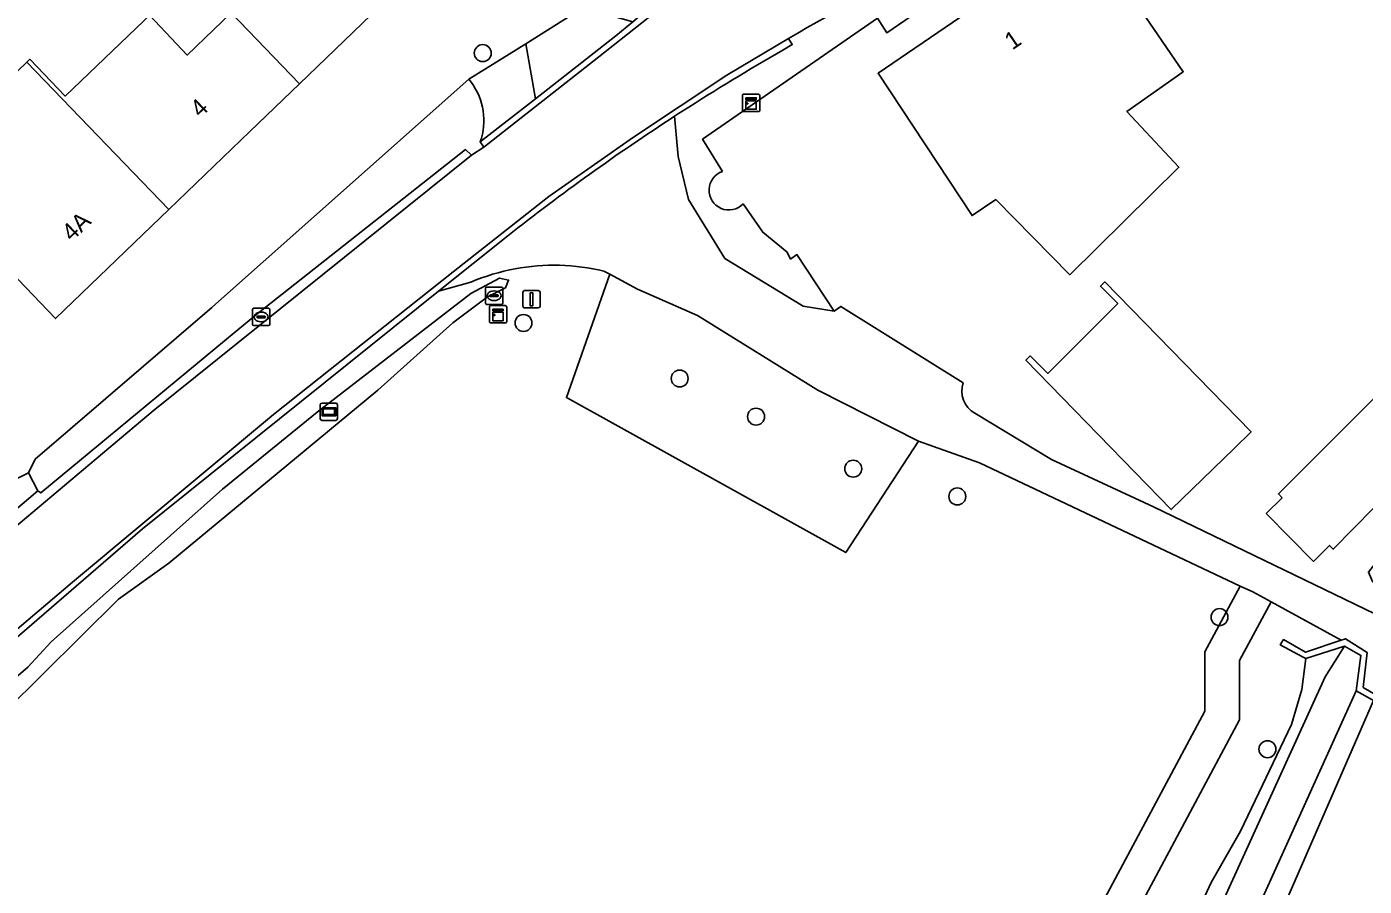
# Model space of a CAD drawing. Extents: x 164494 to 166241, y 382475 to 384495.
# Drawn here: x 165354.5 to 165431.6, y 384025.1 to 384074.7 of the extents above; entities that cross this region are included whole.
import ezdxf

# ---------------------------------------------------------------- set-up
doc = ezdxf.new("R2010")
doc.units = 0
for name, color, linetype in [('IMGEO_Berm_halfverhard', 7, 'Continuous'), ('IMGEO_Berm_open', 7, 'Continuous'), ('IMGEO_Boom', 7, 'Continuous'), ('IMGEO_Erf', 7, 'Continuous'), ('IMGEO_Grasland_agrarisch', 7, 'Continuous'), ('IMGEO_Grasland_overig', 7, 'Continuous'), ('IMGEO_Groenvoorziening', 7, 'Continuous'), ('IMGEO_Kast', 7, 'Continuous'), ('IMGEO_Kolk', 7, 'Continuous'), ('IMGEO_Muur', 7, 'Continuous'), ('IMGEO_Oever', 7, 'Continuous'), ('IMGEO_Pand', 7, 'Continuous'), ('IMGEO_Pand_nummerreeks', 7, 'Continuous'), ('IMGEO_Rijbaan_lokaal_gesloten', 7, 'Continuous'), ('IMGEO_Rioolput', 7, 'Continuous'), ('IMGEO_Verkeersbordpaal', 7, 'Continuous'), ('IMGEO_Voetpad_halfverhard', 7, 'Continuous'), ('IMGEO_Voetpad_open', 7, 'Continuous'), ('IMGEO_Waterloop', 7, 'Continuous'), ('IMGEO_Wegwijzer', 7, 'Continuous')]:
    doc.layers.add(name, color=color, linetype=linetype)

msp = doc.modelspace()

# ---------------------------------------------------------------- linework, layer by layer
at = {"layer": 'IMGEO_Berm_halfverhard'}
for points in [[(165394.648, 384079.364), (165394.369, 384079.637), (165392.734, 384077.813), (165390.73, 384076.059), (165389.436, 384074.97), (165388.458, 384074.147), (165383.832, 384070.529), (165380.649, 384068.04), (165380.854, 384067.745), (165387.482, 384072.953), (165391.605, 384076.232)], [(165398.089, 384073.33), (165398.624, 384073.651), (165398.403, 384074.002), (165394.851, 384071.884), (165389.473, 384068.311), (165384.606, 384064.9), (165379.087, 384060.555), (165368.742, 384052.317), (165357.153, 384042.664), (165349.337, 384036.022), (165342.774, 384030.162), (165342.196, 384029.629), (165342.457, 384029.327), (165343.149, 384029.924), (165343.032, 384030.052), (165361.191, 384045.73)], [(165391.847, 384069.519), (165392.081, 384069.671), (165392.316, 384069.823)], [(165361.191, 384045.73), (165378.251, 384059.429), (165382.228, 384062.623)]]:
    msp.add_lwpolyline(points, dxfattribs=at)
for centre, radius, start, end in [((165462.902, 383960.133), 130.439, 119.79428, 122.76167), ((165462.493, 383960.82), 129.639, 123.02094, 128.25363)]:
    msp.add_arc(centre, radius, start, end, dxfattribs=at)
at = {"layer": 'IMGEO_Berm_open'}
msp.add_lwpolyline([(165380.141, 384067.277), (165379.794, 384067.601), (165367.867, 384058.185), (165366.467, 384057.026), (165355.319, 384047.804), (165355.158, 384047.926), (165353.349, 384046.386), (165353.618, 384046.006), (165353.778, 384045.772), (165361.803, 384052.529)], close=True, dxfattribs=at)
at = {"layer": 'IMGEO_Boom'}
for centre in [(165380.789, 384073.159), (165383.14, 384057.6), (165392.14, 384054.4), (165396.54, 384052.2), (165402.14, 384049.2), (165408.14, 384047.6), (165423.25, 384040.641), (165426.014, 384033.026)]:
    msp.add_circle(centre, 0.489, dxfattribs=at)
at = {"layer": 'IMGEO_Erf'}
for points in [[(165370.222, 384071.391), (165367.373, 384068.646), (165362.702, 384064.146), (165361.201, 384062.699), (165356.175, 384057.856), (165352.706, 384061.457), (165347.988, 384066.354), (165354.518, 384072.645), (165354.686, 384072.807), (165356.732, 384070.685), (165361.259, 384075.024), (165361.593, 384075.344), (165361.693, 384075.439), (165359.686, 384077.533), (165370.419, 384087.822), (165372.426, 384085.728), (165378.512, 384079.379)], [(165424.097, 384050.371), (165420.472, 384046.84), (165412.096, 384055.45), (165412.344, 384055.698), (165413.347, 384054.691), (165417.389, 384058.715), (165416.387, 384059.721), (165416.635, 384059.967), (165425.071, 384051.32)], [(165425.935, 384046.612), (165426.859, 384047.528), (165426.648, 384047.742), (165433.701, 384054.796), (165436.839, 384051.712), (165429.803, 384044.559), (165429.591, 384044.772), (165428.667, 384043.856)]]:
    msp.add_lwpolyline(points, close=True, dxfattribs=at)
for points in [[(165452.198, 384086.5), (165450.367, 384088.075), (165420.581, 384081.409), (165419.584, 384082.942), (165415.596, 384080.216), (165421.157, 384072.086), (165417.913, 384069.799), (165420.915, 384066.582), (165414.624, 384060.384), (165410.357, 384064.715), (165408.991, 384063.791), (165403.577, 384071.996), (165413.421, 384078.728), (165412.998, 384079.325), (165412.511, 384080.132), (165404.074, 384074.333), (165403.548, 384075.178), (165393.462, 384068.193), (165394.614, 384066.341)], [(165379.994, 384071.652), (165383.268, 384073.701), (165386.651, 384075.818), (165386.877, 384076.031), (165390.423, 384079.385), (165392.167, 384081.577)], [(165353.783, 384048.557), (165354.194, 384048.759), (165354.605, 384048.96), (165354.993, 384049.748), (165365.174, 384058.493), (165365.22, 384058.534), (165379.994, 384071.652)], [(165395.797, 384064.474), (165396.928, 384062.833), (165398.326, 384061.675), (165398.534, 384061.287), (165398.894, 384061.546), (165401.043, 384058.287), (165401.42, 384058.556), (165408.472, 384054.156)], [(165409.157, 384052.399), (165413.571, 384049.73), (165419.448, 384047.004), (165432.21, 384040.827), (165432.889, 384042.04), (165432.059, 384042.703), (165431.835, 384043.241), (165432.508, 384044.106), (165433.832, 384046.315), (165434.934, 384048.823), (165437.077, 384050.998), (165439.037, 384053.712), (165441.349, 384057.507)]]:
    msp.add_lwpolyline(points, dxfattribs=at)
for centre, radius, start, end in [((165394.97, 384065.258), 1.14, 108.1874, 316.5323), ((165409.863, 384053.686), 1.468, 161.33029, 241.26826)]:
    msp.add_arc(centre, radius, start, end, dxfattribs=at)
at = {"layer": 'IMGEO_Grasland_agrarisch'}
msp.add_lwpolyline([(165465.876, 383995.163), (165467.034, 384000), (165468.503, 384005.261), (165471.517, 384012.308), (165471.562, 384012.413), (165472.114, 384013.698), (165433.758, 384035.364), (165432.127, 384035.844), (165425.699, 384021.103), (165420.906, 384009.219), (165420.603, 384008.641), (165397.653, 383961.837), (165387.56, 383941.909), (165384.176, 383935.455), (165366.719, 383898.707), (165373.354, 383895.442), (165395.688, 383886.318), (165424.197, 383875.062), (165430.956, 383872.05), (165432.029, 383878.537), (165432.519, 383879.96)], close=True, dxfattribs=at)
at = {"layer": 'IMGEO_Grasland_overig'}
msp.add_lwpolyline([(165406.11, 384000.476), (165424.408, 384034.719), (165424.408, 384038.135), (165426.221, 384041.519), (165425.166, 384042.094), (165424.443, 384042.436), (165422.408, 384038.636), (165422.408, 384035.22), (165404.241, 384001.221)], close=True, dxfattribs=at)
at = {"layer": 'IMGEO_Groenvoorziening'}
for points in [[(165394.614, 384066.341), (165393.462, 384068.193), (165403.548, 384075.178), (165404.074, 384074.333), (165412.511, 384080.132), (165412.998, 384079.325), (165413.421, 384078.728), (165415.596, 384080.216), (165419.584, 384082.942), (165420.581, 384081.409), (165450.367, 384088.075), (165452.198, 384086.5)], [(165383.268, 384073.701), (165379.994, 384071.652)], [(165380.718, 384068.254), (165380.649, 384068.04), (165383.832, 384070.529), (165383.268, 384073.701)], [(165398.403, 384074.002), (165398.624, 384073.651), (165398.089, 384073.33)], [(165392.316, 384069.823), (165392.081, 384069.671), (165391.847, 384069.519), (165392.047, 384067.198), (165392.645, 384064.723), (165394.748, 384061.318), (165399.265, 384058.57), (165401.043, 384058.287), (165398.894, 384061.546), (165398.534, 384061.287), (165398.326, 384061.675), (165396.928, 384062.833), (165395.797, 384064.474)], [(165404.241, 384001.221), (165422.408, 384035.22), (165422.408, 384038.636), (165424.443, 384042.436), (165409.423, 384049.542), (165405.906, 384050.785), (165401.71, 384044.364), (165385.614, 384053.302), (165388.113, 384060.405), (165387.776, 384060.588)], [(165380.105, 384059.954), (165378.251, 384059.429), (165361.191, 384045.73), (165343.032, 384030.052), (165343.149, 384029.924), (165342.457, 384029.327), (165328.664, 384017.425), (165327.921, 384016.784), (165327.858, 384016.829), (165300.992, 383993.615)], [(165333.093, 384019.286), (165354.573, 384037.755), (165355.922, 384039.225), (165365.795, 384048.014), (165371.241, 384052.452), (165380.109, 384059.294), (165381.762, 384060.186), (165382.283, 384060.069), (165382.106, 384059.628), (165381.07, 384059.101), (165379.062, 384057.607), (165374.751, 384053.736), (165362.707, 384043.753), (165359.803, 384041.672), (165346.76, 384028.762), (165343.024, 384025.615), (165348.876, 384023.417)], [(165325.135, 384021.562), (165338.914, 384033.424), (165339.626, 384034.037), (165339.695, 384033.942), (165353.618, 384046.006), (165353.349, 384046.386), (165355.158, 384047.926), (165354.605, 384048.96), (165354.194, 384048.759), (165353.783, 384048.557), (165342.506, 384038.557), (165341.59, 384039.543), (165339.009, 384037.144), (165338.707, 384036.864), (165339.33, 384036.181), (165338.418, 384035.282), (165337.958, 384035.319), (165337.536, 384035.616), (165337.481, 384035.681), (165335.45, 384033.721), (165335.536, 384032.942), (165328.461, 384026.792), (165318.663, 384018.644)]]:
    msp.add_lwpolyline(points, dxfattribs=at)
for points in [[(165388.113, 384060.405), (165385.614, 384053.302), (165401.71, 384044.364), (165405.906, 384050.785), (165400.098, 384053.736), (165393.172, 384058.027), (165389.703, 384059.542)], [(165422.766, 384025.338), (165424.464, 384028.31), (165427.399, 384034.45), (165427.985, 384036.474), (165428.232, 384038.256), (165428.079, 384038.337), (165426.748, 384039.045), (165426.938, 384039.344), (165428.209, 384038.616), (165430.27, 384039.313), (165426.221, 384041.519), (165424.408, 384038.135), (165424.408, 384034.719), (165406.11, 384000.476), (165407.304, 384000), (165408.115, 383999.677), (165409.877, 383999.369), (165410.163, 384000), (165411.412, 384002.76), (165415.793, 384011.089), (165416.075, 384011.624), (165418.888, 384016.972)]]:
    msp.add_lwpolyline(points, close=True, dxfattribs=at)
for centre, radius, start, end in [((165456.825, 383973.925), 115.881, 110.3071, 120.27508), ((165462.902, 383960.133), 130.439, 119.79428, 122.76167), ((165377.139, 384069.268), 3.72, 344.18976, 39.86614), ((165394.97, 384065.258), 1.14, 108.1874, 316.5323), ((165384.913, 384048.624), 12.308, 100.59261, 112.99168), ((165384.899, 384048.625), 12.304, 76.4753, 100.52981)]:
    msp.add_arc(centre, radius, start, end, dxfattribs=at)
at = {"layer": 'IMGEO_Kast'}
for p, q in [((165395.756, 384069.867), (165395.756, 384070.708)), ((165395.756, 384070.708), (165395.756, 384069.867)), ((165395.831, 384070.792), (165396.672, 384070.792)), ((165396.672, 384070.792), (165395.831, 384070.792)), ((165396.756, 384070.717), (165396.756, 384069.876)), ((165396.756, 384069.876), (165396.756, 384070.717)), ((165396.681, 384069.792), (165395.84, 384069.792)), ((165395.84, 384069.792), (165396.681, 384069.792)), ((165381.173, 384057.676), (165381.173, 384058.517)), ((165381.173, 384058.517), (165381.173, 384057.676)), ((165381.248, 384058.601), (165382.089, 384058.601)), ((165382.089, 384058.601), (165381.248, 384058.601)), ((165382.173, 384058.526), (165382.173, 384057.685)), ((165382.173, 384057.685), (165382.173, 384058.526)), ((165382.098, 384057.601), (165381.257, 384057.601)), ((165381.257, 384057.601), (165382.098, 384057.601))]:
    msp.add_line(p, q, dxfattribs=at)
for points in [[(165395.951, 384070.582), (165396.551, 384070.582), (165396.551, 384070.497), (165395.951, 384070.497), (165395.951, 384070.582)], [(165395.951, 384070.407), (165396.551, 384070.407), (165396.551, 384069.918), (165395.951, 384069.918), (165395.951, 384070.407)], [(165381.368, 384058.391), (165381.968, 384058.391), (165381.968, 384058.306), (165381.368, 384058.306), (165381.368, 384058.391)], [(165381.368, 384058.216), (165381.968, 384058.216), (165381.968, 384057.727), (165381.368, 384057.727), (165381.368, 384058.216)]]:
    msp.add_lwpolyline(points, dxfattribs=at)
for centre in [(165396.035, 384070.256), (165381.452, 384058.065)]:
    msp.add_circle(centre, 0.0377, dxfattribs=at)
for centre, start, end in [((165395.834, 384070.714), 92.4484, 184.28452), ((165395.834, 384070.714), 92.4484, 184.28452), ((165396.678, 384070.714), 2.4484, 94.28452), ((165396.678, 384070.714), 2.4484, 94.28452), ((165395.834, 384069.87), 182.4484, 274.28452), ((165395.834, 384069.87), 182.4484, 274.28452), ((165396.678, 384069.87), 272.4484, 4.28452), ((165396.678, 384069.87), 272.4484, 4.28452), ((165381.251, 384058.523), 92.4484, 184.28452), ((165381.251, 384058.523), 92.4484, 184.28452), ((165382.095, 384058.523), 2.4484, 94.28452), ((165382.095, 384058.523), 2.4484, 94.28452), ((165381.251, 384057.679), 182.4484, 274.28452), ((165381.251, 384057.679), 182.4484, 274.28452), ((165382.095, 384057.679), 272.4484, 4.28452), ((165382.095, 384057.679), 272.4484, 4.28452)]:
    msp.add_arc(centre, 0.0779, start, end, dxfattribs=at)
at = {"layer": 'IMGEO_Kolk'}
for p, q in [((165367.52, 384057.521), (165367.52, 384058.373)), ((165367.595, 384058.447), (165368.447, 384058.447)), ((165368.008, 384058.227), (165368.033, 384058.227)), ((165368.521, 384058.373), (165368.521, 384057.521)), ((165368.447, 384057.447), (165367.595, 384057.447)), ((165367.779, 384057.941), (165367.779, 384057.953)), ((165368.217, 384057.904), (165367.819, 384057.904)), ((165367.822, 384057.99), (165368.22, 384057.99)), ((165368.031, 384057.667), (165368.006, 384057.667)), ((165368.263, 384057.953), (165368.263, 384057.941))]:
    msp.add_line(p, q, dxfattribs=at)
for points in [[(165367.52, 384057.521), (165367.52, 384058.373)], [(165367.595, 384058.447), (165368.447, 384058.447)], [(165368.521, 384058.373), (165368.521, 384057.521)], [(165368.447, 384057.447), (165367.595, 384057.447)]]:
    msp.add_lwpolyline(points, dxfattribs=at)
for centre, radius, start, end in [((165367.597, 384058.371), 0.0765, 91.55205, 178.44795), ((165367.597, 384058.371), 0.0765, 91.55205, 178.44795), ((165368.445, 384058.371), 0.0765, 1.55205, 88.44795), ((165368.445, 384058.371), 0.0765, 1.55205, 88.44795), ((165367.597, 384057.523), 0.0765, 181.55205, 268.44795), ((165367.597, 384057.523), 0.0765, 181.55205, 268.44795), ((165367.819, 384057.95), 0.0403, 85.87752, 175.75265), ((165367.816, 384057.94), 0.0366, 178.93798, 274.71019), ((165368.22, 384057.947), 0.043, 264.86636, 352.45326), ((165368.224, 384057.952), 0.0386, 1.73085, 96.63898), ((165368.445, 384057.523), 0.0765, 271.55205, 358.44795), ((165368.445, 384057.523), 0.0765, 271.55205, 358.44795)]:
    msp.add_arc(centre, radius, start, end, dxfattribs=at)
for centre, major_axis, ratio, start_param, end_param in [((165368.007, 384057.947), (-0.387, 0.002), 0.722429, 4.712389, 7.853982), ((165368.032, 384057.947), (-0.39, 0.002), 0.717154, 1.570796, 4.712389)]:
    msp.add_ellipse(centre, major_axis=major_axis, ratio=ratio, start_param=start_param, end_param=end_param, dxfattribs=at)
at = {"layer": 'IMGEO_Muur'}
msp.add_lwpolyline([(165428.079, 384038.337), (165428.232, 384038.256), (165430.446, 384038.958), (165431.397, 384038.432), (165431.116, 384036.401), (165432.127, 384035.844), (165432.264, 384036.165), (165431.524, 384036.587), (165431.768, 384038.601), (165430.503, 384039.392), (165430.27, 384039.313), (165428.209, 384038.616), (165426.938, 384039.344), (165426.748, 384039.045)], close=True, dxfattribs=at)
at = {"layer": 'IMGEO_Oever'}
for points in [[(165430.446, 384038.958), (165428.232, 384038.256), (165427.985, 384036.474), (165427.399, 384034.45), (165424.464, 384028.31), (165422.766, 384025.338), (165418.888, 384016.972), (165416.075, 384011.624), (165415.793, 384011.089), (165417.142, 384010.409), (165429.344, 384037.193)], [(165425.699, 384021.103), (165432.127, 384035.844), (165431.116, 384036.401), (165419.214, 384010.042), (165418.943, 384009.502), (165420.603, 384008.641), (165420.906, 384009.219)]]:
    msp.add_lwpolyline(points, close=True, dxfattribs=at)
at = {"layer": 'IMGEO_Pand'}
for points in [[(165378.512, 384079.379), (165372.426, 384085.728), (165370.419, 384087.822), (165359.686, 384077.533), (165361.693, 384075.439), (165361.593, 384075.344), (165363.752, 384073.045), (165366.29, 384075.484), (165370.222, 384071.391)], [(165413.421, 384078.728), (165403.577, 384071.996), (165408.991, 384063.791), (165410.357, 384064.715), (165414.624, 384060.384), (165420.915, 384066.582), (165417.913, 384069.799), (165421.157, 384072.086), (165415.596, 384080.216)], [(165362.702, 384064.146), (165367.373, 384068.646), (165370.222, 384071.391), (165366.29, 384075.484), (165363.752, 384073.045), (165361.593, 384075.344), (165361.259, 384075.024), (165356.732, 384070.685), (165354.686, 384072.807), (165354.518, 384072.645)], [(165362.702, 384064.146), (165354.518, 384072.645), (165347.988, 384066.354), (165352.706, 384061.457), (165356.175, 384057.856), (165361.201, 384062.699)], [(165424.097, 384050.371), (165425.071, 384051.32), (165416.635, 384059.967), (165416.387, 384059.721), (165417.389, 384058.715), (165413.347, 384054.691), (165412.344, 384055.698), (165412.096, 384055.45), (165420.472, 384046.84)], [(165425.935, 384046.612), (165428.667, 384043.856), (165429.591, 384044.772), (165429.803, 384044.559), (165436.839, 384051.712), (165433.701, 384054.796), (165426.648, 384047.742), (165426.859, 384047.528)]]:
    msp.add_lwpolyline(points, close=True, dxfattribs=at)
at = {"layer": 'IMGEO_Rijbaan_lokaal_gesloten'}
msp.add_lwpolyline([(165391.605, 384076.232), (165387.482, 384072.953), (165380.854, 384067.745), (165380.141, 384067.277), (165361.803, 384052.529), (165353.778, 384045.772), (165339.3, 384032.977), (165339.311, 384032.965), (165342.18, 384029.647), (165342.192, 384029.633), (165342.196, 384029.629), (165342.774, 384030.162), (165349.337, 384036.022), (165357.153, 384042.664), (165368.742, 384052.317), (165379.087, 384060.555), (165384.606, 384064.9), (165389.473, 384068.311), (165394.851, 384071.884), (165398.403, 384074.002)], dxfattribs=at)
msp.add_arc((165456.825, 383973.925), 115.881, 110.3071, 120.27508, dxfattribs=at)
at = {"layer": 'IMGEO_Rioolput'}
for p, q in [((165381.019, 384059.673), (165381.871, 384059.673)), ((165380.944, 384058.747), (165380.944, 384059.599)), ((165381.203, 384059.167), (165381.203, 384059.179)), ((165381.641, 384059.13), (165381.243, 384059.13)), ((165381.246, 384059.216), (165381.644, 384059.216)), ((165381.455, 384058.893), (165381.43, 384058.893)), ((165381.432, 384059.453), (165381.457, 384059.453)), ((165381.687, 384059.179), (165381.687, 384059.167)), ((165381.945, 384059.599), (165381.945, 384058.747)), ((165381.871, 384058.673), (165381.019, 384058.673))]:
    msp.add_line(p, q, dxfattribs=at)
for points in [[(165381.019, 384059.673), (165381.871, 384059.673)], [(165380.944, 384058.747), (165380.944, 384059.599)], [(165381.945, 384059.599), (165381.945, 384058.747)], [(165381.871, 384058.673), (165381.019, 384058.673)]]:
    msp.add_lwpolyline(points, dxfattribs=at)
for centre, radius, start, end in [((165381.021, 384059.597), 0.0765, 91.55205, 178.44795), ((165381.021, 384059.597), 0.0765, 91.55205, 178.44795), ((165381.869, 384059.597), 0.0765, 1.55205, 88.44795), ((165381.869, 384059.597), 0.0765, 1.55205, 88.44795), ((165381.243, 384059.176), 0.0403, 85.87752, 175.75265), ((165381.24, 384059.166), 0.0366, 178.93798, 274.71019), ((165381.644, 384059.173), 0.043, 264.86636, 352.45326), ((165381.648, 384059.178), 0.0386, 1.73085, 96.63898), ((165381.021, 384058.749), 0.0765, 181.55205, 268.44795), ((165381.021, 384058.749), 0.0765, 181.55205, 268.44795), ((165381.869, 384058.749), 0.0765, 271.55205, 358.44795), ((165381.869, 384058.749), 0.0765, 271.55205, 358.44795)]:
    msp.add_arc(centre, radius, start, end, dxfattribs=at)
for centre, major_axis, ratio, start_param, end_param in [((165381.431, 384059.173), (-0.387, 0.002), 0.722429, 4.712389, 7.853982), ((165381.456, 384059.173), (-0.39, 0.002), 0.717154, 1.570796, 4.712389)]:
    msp.add_ellipse(centre, major_axis=major_axis, ratio=ratio, start_param=start_param, end_param=end_param, dxfattribs=at)
at = {"layer": 'IMGEO_Verkeersbordpaal'}
for p, q in [((165383.103, 384058.572), (165383.103, 384059.372)), ((165383.103, 384059.372), (165383.103, 384058.572)), ((165383.203, 384059.472), (165383.993, 384059.472)), ((165383.993, 384059.472), (165383.203, 384059.472)), ((165384.093, 384059.372), (165384.093, 384058.572)), ((165384.093, 384058.572), (165384.093, 384059.372)), ((165383.993, 384058.472), (165383.203, 384058.472)), ((165383.203, 384058.472), (165383.993, 384058.472))]:
    msp.add_line(p, q, dxfattribs=at)
msp.add_lwpolyline([(165383.523, 384059.347), (165383.673, 384059.347), (165383.673, 384058.597), (165383.523, 384058.597), (165383.523, 384059.347)], dxfattribs=at)
for centre, start, end in [((165383.203, 384059.372), 90, 180), ((165383.203, 384059.372), 90, 180), ((165383.993, 384059.372), 0, 90), ((165383.993, 384059.372), 360, 90), ((165383.203, 384058.572), 180, 270), ((165383.203, 384058.572), 180, 270), ((165383.993, 384058.572), 270, 0), ((165383.993, 384058.572), 270, 0)]:
    msp.add_arc(centre, 0.1, start, end, dxfattribs=at)
at = {"layer": 'IMGEO_Voetpad_halfverhard'}
for points in [[(165408.472, 384054.156), (165401.42, 384058.556), (165401.043, 384058.287), (165399.265, 384058.57), (165394.748, 384061.318), (165392.645, 384064.723), (165392.047, 384067.198), (165391.847, 384069.519)], [(165382.228, 384062.623), (165378.251, 384059.429), (165380.105, 384059.954)], [(165387.776, 384060.588), (165388.113, 384060.405), (165389.703, 384059.542), (165393.172, 384058.027), (165400.098, 384053.736), (165405.906, 384050.785), (165409.423, 384049.542), (165424.443, 384042.436), (165425.166, 384042.094), (165426.221, 384041.519), (165430.27, 384039.313), (165430.503, 384039.392), (165431.768, 384038.601), (165431.524, 384036.587), (165432.264, 384036.165)], [(165419.448, 384047.004), (165413.571, 384049.73), (165409.157, 384052.399)], [(165432.21, 384040.827), (165419.448, 384047.004)]]:
    msp.add_lwpolyline(points, dxfattribs=at)
for centre, radius, start, end in [((165462.493, 383960.82), 129.639, 123.02094, 128.25363), ((165384.913, 384048.624), 12.308, 100.59261, 112.99168), ((165384.899, 384048.625), 12.304, 76.4753, 100.52981), ((165409.863, 384053.686), 1.468, 161.33029, 241.26826)]:
    msp.add_arc(centre, radius, start, end, dxfattribs=at)
at = {"layer": 'IMGEO_Voetpad_open'}
msp.add_lwpolyline([(165388.458, 384074.147), (165389.436, 384074.97), (165388.208, 384075.306), (165387.345, 384075.542), (165386.877, 384076.031), (165386.651, 384075.818), (165383.268, 384073.701), (165383.832, 384070.529)], close=True, dxfattribs=at)
for points in [[(165379.994, 384071.652), (165365.22, 384058.534), (165365.174, 384058.493), (165354.993, 384049.748), (165354.605, 384048.96), (165355.158, 384047.926), (165355.319, 384047.804), (165366.467, 384057.026), (165367.867, 384058.185)], [(165367.867, 384058.185), (165379.794, 384067.601), (165380.141, 384067.277), (165380.854, 384067.745), (165380.649, 384068.04), (165380.718, 384068.254)]]:
    msp.add_lwpolyline(points, dxfattribs=at)
msp.add_arc((165377.139, 384069.268), 3.72, 344.18976, 39.86614, dxfattribs=at)
at = {"layer": 'IMGEO_Waterloop'}
msp.add_lwpolyline([(165348.876, 384023.417), (165343.024, 384025.615), (165346.76, 384028.762), (165359.803, 384041.672), (165362.707, 384043.753), (165374.751, 384053.736), (165379.062, 384057.607), (165381.07, 384059.101), (165382.106, 384059.628), (165382.283, 384060.069), (165381.762, 384060.186), (165380.109, 384059.294), (165371.241, 384052.452), (165365.795, 384048.014), (165355.922, 384039.225), (165354.573, 384037.755), (165333.093, 384019.286)], dxfattribs=at)
msp.add_lwpolyline([(165431.116, 384036.401), (165431.397, 384038.432), (165430.446, 384038.958), (165429.344, 384037.193), (165417.142, 384010.409), (165418.943, 384009.502), (165419.214, 384010.042)], close=True, dxfattribs=at)
at = {"layer": 'IMGEO_Wegwijzer'}
for p, q in [((165371.428, 384052.083), (165371.428, 384052.883)), ((165371.428, 384052.883), (165371.428, 384052.083)), ((165371.528, 384052.983), (165372.318, 384052.983)), ((165372.318, 384052.983), (165371.528, 384052.983)), ((165372.418, 384052.883), (165372.418, 384052.083)), ((165372.418, 384052.083), (165372.418, 384052.883)), ((165372.318, 384051.983), (165371.528, 384051.983)), ((165371.528, 384051.983), (165372.318, 384051.983))]:
    msp.add_line(p, q, dxfattribs=at)
for points in [[(165371.529, 384052.715), (165372.317, 384052.715), (165372.317, 384052.251), (165371.529, 384052.251), (165371.529, 384052.715)], [(165371.594, 384052.65), (165371.594, 384052.316), (165372.252, 384052.316), (165372.252, 384052.65), (165371.594, 384052.65)]]:
    msp.add_lwpolyline(points, dxfattribs=at)
for centre, start, end in [((165371.528, 384052.883), 90, 180), ((165371.528, 384052.883), 90, 180), ((165372.318, 384052.883), 0, 90), ((165372.318, 384052.883), 360, 90), ((165371.528, 384052.083), 180, 270), ((165371.528, 384052.083), 180, 270), ((165372.318, 384052.083), 270, 0), ((165372.318, 384052.083), 270, 0)]:
    msp.add_arc(centre, 0.1, start, end, dxfattribs=at)

# ---------------------------------------------------------------- texts
at = {"layer": 'IMGEO_Pand_nummerreeks'}
for s, rotation, p in [('1', 34.36889, (165411.305, 384073.307)), ('4', 43.93645, (165364.518, 384069.395)), ('4A', 43.93739, (165357.111, 384062.257))]:
    msp.add_text(s, height=1, rotation=rotation, dxfattribs=at).set_placement(p)

doc.saveas('drawing.dxf')
